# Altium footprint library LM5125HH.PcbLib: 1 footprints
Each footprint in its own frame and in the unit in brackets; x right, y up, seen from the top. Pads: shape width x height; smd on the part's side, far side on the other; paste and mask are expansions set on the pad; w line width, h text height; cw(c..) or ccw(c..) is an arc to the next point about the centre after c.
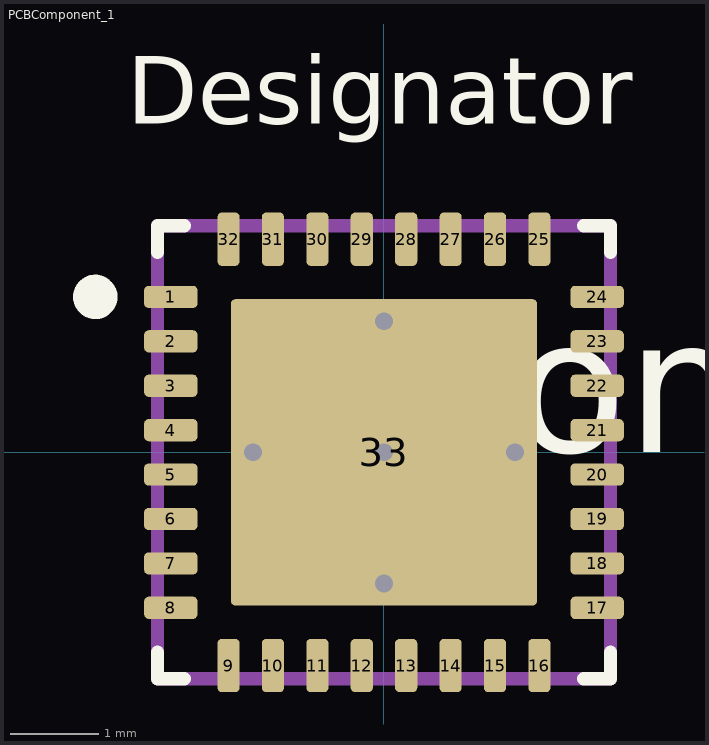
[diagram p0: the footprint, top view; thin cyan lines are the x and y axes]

## PCBComponent_1 [mm]
pads (33):
  rrect40% 0.6x0.25 smd paste+0 mask+0: 1(-2.4,1.75) 2(-2.4,1.25) 3(-2.4,0.75) 4(-2.4,0.25) 5(-2.4,-0.25) 6(-2.4,-0.75) 7(-2.4,-1.25) 8(-2.4,-1.75) 17(2.4,-1.75) 18(2.4,-1.25) 19(2.4,-0.75) 20(2.4,-0.25) 21(2.4,0.25) 22(2.4,0.75) 23(2.4,1.25) 24(2.4,1.75)
  rrect40% 0.25x0.6 smd paste+0 mask+0: 9(-1.75,-2.4) 10(-1.25,-2.4) 11(-0.75,-2.4) 12(-0.25,-2.4) 13(0.25,-2.4) 14(0.75,-2.4) 15(1.25,-2.4) 16(1.75,-2.4) 25(1.75,2.4) 26(1.25,2.4) 27(0.75,2.4) 28(0.25,2.4) 29(-0.25,2.4) 30(-0.75,2.4) 31(-1.25,2.4) 32(-1.75,2.4)
  rrect3% 3.45x3.45 smd paste-1000 mask+0: 33(0,0)
via 0,1.475 diameter 0.5 hole 0.2
via 0,0 diameter 0.5 hole 0.2
via 0,-1.475 diameter 0.5 hole 0.2
via -1.475,0 diameter 0.5 hole 0.2
via 1.475,0 diameter 0.5 hole 0.2
Top Overlay:
  circle w0.25: c-3.25,1.75 r0.125
  lines w0.15: -2.55,-2.25 -2.55,-2.55 -2.25,-2.55 ; -2.55,2.25 -2.55,2.55 -2.25,2.55 ; 2.25,-2.55 2.55,-2.55 2.55,-2.25 ; 2.25,2.55 2.55,2.55 2.55,2.25
  text "Designator" at -2.897,3.703 h0.76
  text "Comment" at 0,0 h1.52
Top Paste:
  region: -1.54,1.59 -0.15,1.59 -0.14,1.59 -0.122,1.582 -0.108,1.568 -0.1,1.55 -0.1,1.54 -0.1,0.15 -0.1,0.14 -0.108,0.122 -0.122,0.108 -0.14,0.1 -0.15,0.1 -1.54,0.1 -1.55,0.1 -1.568,0.108 -1.582,0.122 -1.59,0.14 -1.59,0.15 -1.59,1.54 -1.59,1.55 -1.582,1.568 -1.568,1.582 -1.55,1.59
  region: 0.1,0.15 0.1,1.54 0.1,1.55 0.108,1.568 0.122,1.582 0.14,1.59 0.15,1.59 1.54,1.59 1.55,1.59 1.568,1.582 1.582,1.568 1.59,1.55 1.59,1.54 1.59,0.15 1.59,0.14 1.582,0.122 1.568,0.108 1.55,0.1 1.54,0.1 0.15,0.1 0.14,0.1 0.122,0.108 0.108,0.122 0.1,0.14
  region: -1.54,-1.59 -1.55,-1.59 -1.568,-1.582 -1.582,-1.568 -1.59,-1.55 -1.59,-1.54 -1.59,-0.15 -1.59,-0.14 -1.582,-0.122 -1.568,-0.108 -1.55,-0.1 -1.54,-0.1 -0.15,-0.1 -0.14,-0.1 -0.122,-0.108 -0.108,-0.122 -0.1,-0.14 -0.1,-0.15 -0.1,-1.54 -0.1,-1.55 -0.108,-1.568 -0.122,-1.582 -0.14,-1.59 -0.15,-1.59
  region: 0.1,-1.54 0.1,-0.15 0.1,-0.14 0.108,-0.122 0.122,-0.108 0.14,-0.1 0.15,-0.1 1.54,-0.1 1.55,-0.1 1.568,-0.108 1.582,-0.122 1.59,-0.14 1.59,-0.15 1.59,-1.54 1.59,-1.55 1.582,-1.568 1.568,-1.582 1.55,-1.59 1.54,-1.59 0.15,-1.59 0.14,-1.59 0.122,-1.582 0.108,-1.568 0.1,-1.55
M5 Assembly Top:
  lines w0.15: -2.55,-2.55 2.55,-2.55 2.55,2.55 -2.55,2.55 -2.55,-2.55
  text ".Designator" at 0.05,0.217 h0.5
3D body "IC_THVD4421RHB_VQFN32.STEP": height 0.25, standoff 0, extent -2.8,-2.8 2.8,2.8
